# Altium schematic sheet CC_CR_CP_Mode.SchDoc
size A3; SheetNumber: 1; SheetTotal: 2
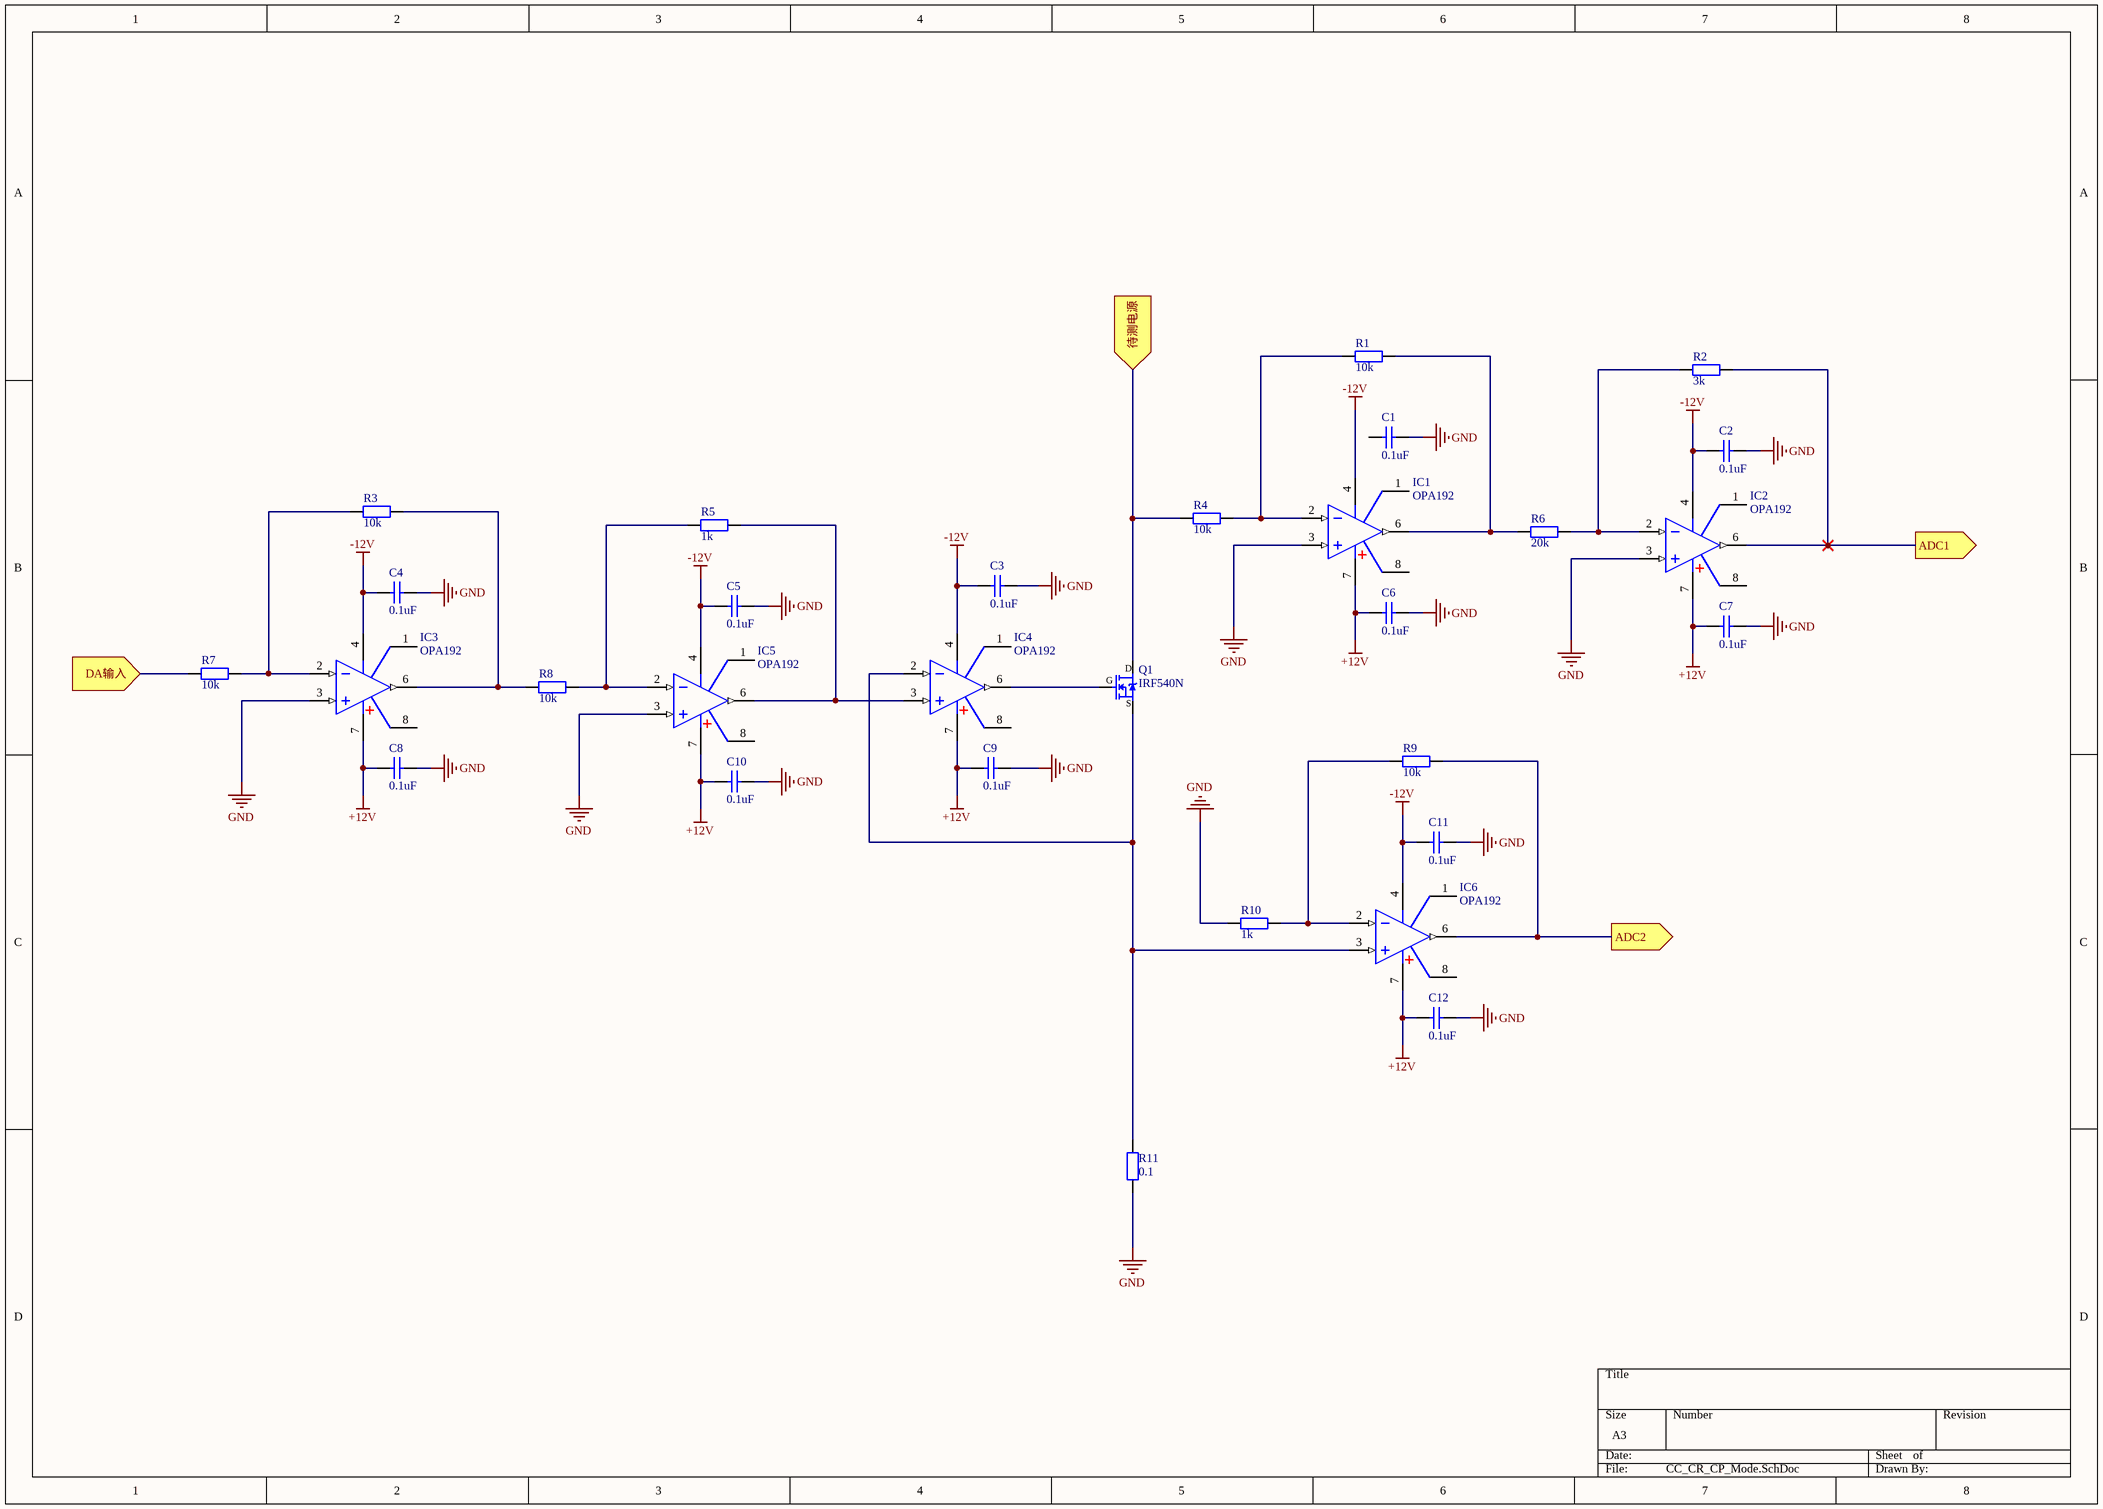
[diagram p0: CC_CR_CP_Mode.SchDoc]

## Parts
C1  0.1uF  [瓷片电容]
C2  0.1uF  [瓷片电容]
C3  0.1uF  [瓷片电容]
C4  0.1uF  [瓷片电容]
C5  0.1uF  [瓷片电容]
C6  0.1uF  [瓷片电容]
C7  0.1uF  [瓷片电容]
C8  0.1uF  [瓷片电容]
C9  0.1uF  [瓷片电容]
C10  0.1uF  [瓷片电容]
C11  0.1uF  [瓷片电容]
C12  0.1uF  [瓷片电容]
IC1  OPA192  [SOP8_N]
IC2  OPA192  [SOP8_N]
IC3  OPA192  [SOP8_N]
IC4  OPA192  [SOP8_N]
IC5  OPA192  [SOP8_N]
IC6  OPA192  [SOP8_N]
Q1  IRF540N  [TO263-3B]
R1  10k  [RS 1/4W]
R2  3k  [RS 1/4W]
R3  10k  [RS 1/4W]
R4  10k  [RS 1/4W]
R5  1k  [RS 1/4W]
R6  20k  [RS 1/4W]
R7  10k  [RS 1/4W]
R8  10k  [RS 1/4W]
R9  10k  [RS 1/4W]
R10  1k  [RS 1/4W]
R11  0.1  [RS 1/4W]

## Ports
ADC1 (out), ADC2 (out), DA输入 (in), 待测电源 (in)

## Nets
+12V: C6.1 C7.1 C8.1 C9.1 C10.1 C12.1 IC1.7(V+) IC2.7(V+) IC3.7(V+) IC4.7(V+) IC5.7(V+) IC6.7(V+)
-12V: C2.1 C3.1 C4.1 C5.1 C11.1 IC1.4(V-) IC2.4(V-) IC3.4(V-) IC4.4(V-) IC5.4(V-) IC6.4(V-)
GND: C1.2 C2.2 C3.2 C4.2 C5.2 C6.2 C7.2 C8.2 C9.2 C10.2 C11.2 C12.2 IC1.3(IN+) IC2.3(IN+) IC3.3(IN+) IC5.3(IN+) R10.1 R11.1
ADC1: IC2.6(OUT) R2.2 ; port ADC1
ADC2: IC6.6(OUT) R9.2 ; port ADC2
DA输入: R7.1 ; port DA输入
待测电源: Q1.2(S) R4.1 ; port 待测电源
NetIC1_2: IC1.2(IN-) R1.1 R4.2
NetIC1_6: IC1.6(OUT) R1.2 R6.1
NetIC2_2: IC2.2(IN-) R2.1 R6.2
NetIC3_2: IC3.2(IN-) R3.1 R7.2
NetIC3_6: IC3.6(OUT) R3.2 R8.1
NetIC4_2: IC4.2(IN-) IC6.3(IN+) Q1.3(D) R11.2
NetIC4_3: IC4.3(IN+) IC5.6(OUT) R5.2
NetIC4_6: IC4.6(OUT) Q1.1(G)
NetIC5_2: IC5.2(IN-) R5.1 R8.2
NetIC6_2: IC6.2(IN-) R9.1 R10.2

Not connected (* = marked no-connect by the designer): C1 1; IC1 1 8; IC2 1 8; IC3 1 8; IC4 1 8; IC5 1 8; IC6 1 8

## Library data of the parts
C1-C12 = Cap_DIP: 直插电容; Value: 100nF; Voltage: 63V
IC1-IC6 = OPA192: High-Voltage, Rail-to-Rail Input/Output, 5µV, 0.2µV/˚C, Precision Operational Amplifier; BOM名称: 单路精密运放; 版权归属: 源创客
Q1 = IRF540N: N沟场 100V/22A; BOM名称: 效应管; 版权归属: 源创客
R1-R11 = Res_DIP: 直插电阻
